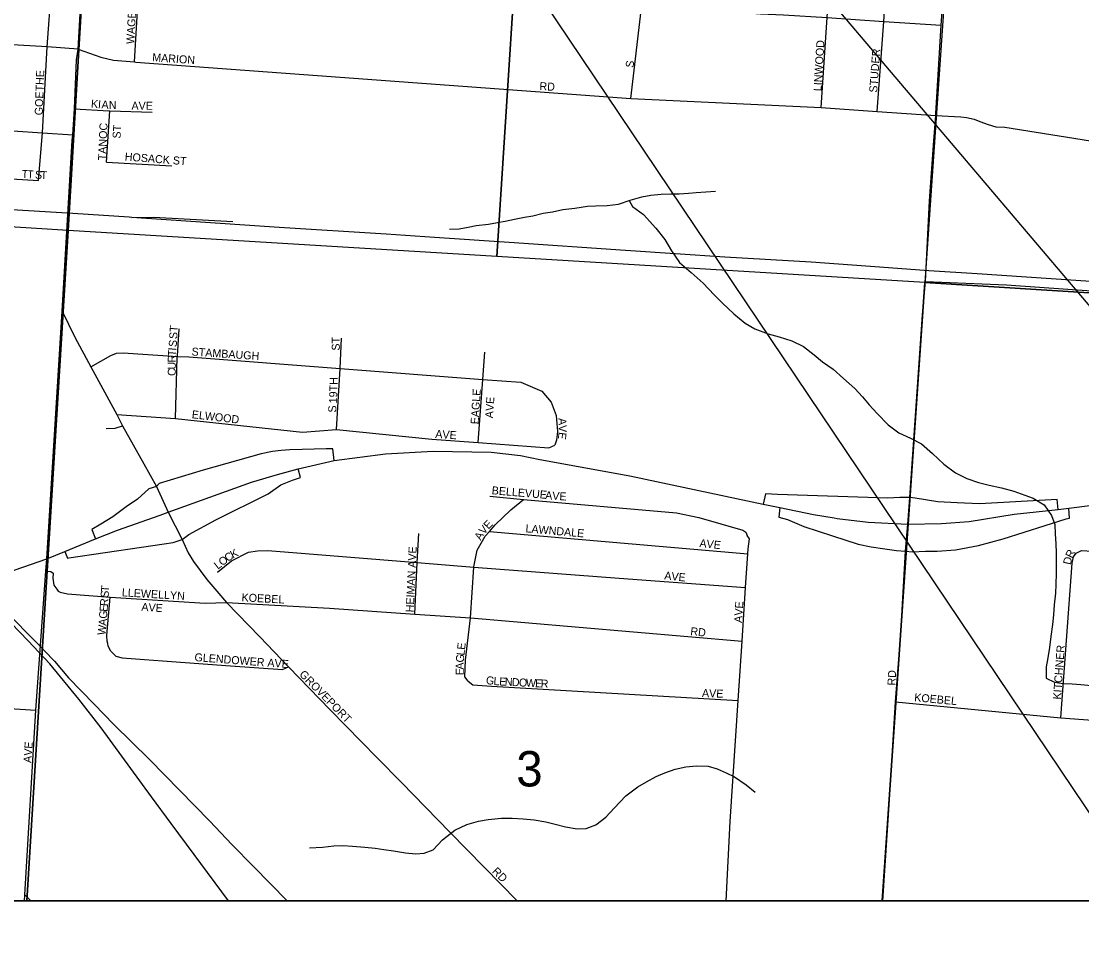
# Model space of a CAD drawing. Extents: x 0 to 34, y -6.2 to 22.
# Drawn here: x 7.442 to 8.697, y 14.325 to 15.431 of the extents above; entities that cross this region are included whole.
import ezdxf

# ---------------------------------------------------------------- set-up
doc = ezdxf.new("R2010")
doc.units = 0
for name, color, linetype in [('GM_X_City_Street', 7, 'Continuous'), ('GM_X_City_Street_Text', 7, 'Continuous'), ('GM_X_Corporation', 7, 'Continuous'), ('GM_X_Interchange_Ramps', 7, 'Continuous'), ('GM_X_Minor_River', 7, 'Continuous'), ('GM_X_Rail_Line', 7, 'Continuous'), ('GM_X_Section', 7, 'Continuous'), ('GM_X_Section_Text', 7, 'Continuous'), ('GM_X_State_Route', 7, 'Continuous'), ('SH_Data', 7, 'Continuous')]:
    doc.layers.add(name, color=color, linetype=linetype)

msp = doc.modelspace()

# ---------------------------------------------------------------- linework, layer by layer
at = {"layer": 'GM_X_City_Street'}
for points in [[(8.163, 15.3396), (8.176, 15.4504), (8.1782, 15.5559), (8.1782, 15.557), (8.1854, 15.613), (8.1897, 15.6855), (8.2011, 15.8649), (8.2084, 15.987), (8.2188, 16.1604)], [(8.524, 15.3221), (8.5303, 15.4266), (8.5334, 15.4708), (8.5376, 15.5324), (8.5419, 15.5889), (8.5466, 15.6592), (8.5554, 15.7853), (8.5577, 15.8394), (8.5686, 15.9805), (8.5712, 16.0212), (8.5785, 16.1374)], [(8.3883, 15.329), (8.3954, 15.4354), (8.4024, 15.5434)], [(8.4546, 15.3243), (8.4624, 15.4307), (8.4695, 15.5383)], [(7.5755, 15.383), (7.5841, 15.524)], [(7.4622, 15.2425), (7.4669, 15.299), (7.4724, 15.4007), (7.4775, 15.4705), (7.4788, 15.4923)], [(7.4902, 15.0879), (7.5019, 15.29), (7.5026, 15.2966), (7.5045, 15.3274), (7.5072, 15.3854), (7.5089, 15.3982), (7.5131, 15.4682)], [(8.1514, 15.4504), (8.176, 15.4504), (8.2417, 15.4455), (8.3166, 15.4399), (8.3436, 15.4388), (8.3954, 15.4354), (8.4624, 15.4307), (8.5303, 15.4266)], [(7.5089, 15.3982), (7.4724, 15.4007), (7.4381, 15.4029), (7.4099, 15.4045), (7.3643, 15.4074), (7.3253, 15.41), (7.3031, 15.4113), (7.2316, 15.4159), (7.1738, 15.4196), (7.1238, 15.4229), (7.0334, 15.4291), (6.9246, 15.436)], [(7.5089, 15.3982), (7.5358, 15.3885), (7.551, 15.3852), (7.5755, 15.383), (7.5774, 15.3828)], [(7.5774, 15.3828), (8.163, 15.3396), (8.3883, 15.329), (8.4546, 15.3243), (8.5238, 15.3195)], [(6.9278, 15.3347), (6.9941, 15.3301), (7.0268, 15.3278), (7.0575, 15.326), (7.088, 15.324), (7.1174, 15.3219), (7.1555, 15.3196), (7.1669, 15.3189), (7.2254, 15.3148), (7.2752, 15.3117), (7.3191, 15.3089), (7.358, 15.3062), (7.4217, 15.3018), (7.4319, 15.3013), (7.4669, 15.299), (7.5026, 15.2966)], [(7.5045, 15.3274), (7.5454, 15.3251)], [(7.5425, 15.2645), (7.5466, 15.3251)], [(7.5454, 15.3251), (7.5466, 15.3251), (7.5966, 15.3237)], [(8.5118, 15.1232), (8.5166, 15.2187), (8.5215, 15.2895), (8.5238, 15.3195), (8.524, 15.3221)], [(8.5238, 15.3195), (8.5536, 15.318), (8.5604, 15.3173), (8.5692, 15.3152), (8.5761, 15.3123), (8.586, 15.3089), (8.5948, 15.3063), (8.6058, 15.3058), (8.707, 15.2895), (8.7685, 15.2877), (8.792, 15.2886), (8.8262, 15.3), (8.8384, 15.3033), (8.8573, 15.3032), (8.8971, 15.3013), (9.0311, 15.3002)], [(7.5425, 15.2645), (7.6197, 15.2599)], [(7.4034, 15.2468), (7.4174, 15.2454), (7.4622, 15.2425)], [(8.4932, 14.8674), (8.5082, 15.0838), (8.5118, 15.1232)], [(8.5118, 15.1232), (8.6075, 15.1193), (9.0153, 15.0903), (9.0755, 15.0865)], [(7.4461, 14.3971), (7.459, 14.6158), (7.4708, 14.7803), (7.4718, 14.795), (7.4902, 15.0879)], [(7.4902, 15.0879), (7.5052, 15.0572), (7.5239, 15.0222), (7.5548, 14.9656), (7.5615, 14.9525), (7.5869, 14.9072)], [(7.6265, 15.0352), (7.6286, 15.067)], [(7.8148, 14.9479), (7.8191, 15.0202), (7.8205, 15.0561)], [(7.5239, 15.0222), (7.5477, 15.0354), (7.5544, 15.0382), (7.5622, 15.0388), (7.6264, 15.0343), (7.6401, 15.034), (7.8191, 15.0202), (7.988, 15.0072), (8.033, 15.0038), (8.0577, 14.9932), (8.0687, 14.9803), (8.0745, 14.9644), (8.0761, 14.9454), (8.075, 14.9352), (8.0731, 14.9295)], [(7.9873, 14.9965), (7.9873, 14.9966), (7.988, 15.0072), (7.9904, 15.0393)], [(7.6243, 14.9611), (7.6263, 15.0334), (7.6264, 15.0343), (7.6265, 15.0352)], [(7.9825, 14.9325), (7.9873, 14.9965)], [(7.5548, 14.9656), (7.6243, 14.9611), (7.7746, 14.9448), (7.8148, 14.9479), (7.9275, 14.9366), (7.9825, 14.9325), (8.0659, 14.9264), (8.0731, 14.9295)], [(7.5421, 14.949), (7.5527, 14.9497), (7.5615, 14.9525)], [(7.5869, 14.9072), (7.6019, 14.8804), (7.6155, 14.8501), (7.6322, 14.8177), (7.6393, 14.8019), (7.6456, 14.7917), (7.6613, 14.7706), (7.6731, 14.7568), (7.6847, 14.7433)], [(7.9706, 14.6501), (7.9664, 14.6554), (7.9674, 14.6748), (7.9733, 14.7249), (7.9773, 14.7852), (7.9773, 14.7853), (7.981, 14.805), (7.9908, 14.8218), (7.9956, 14.8272), (8.0025, 14.8351), (8.021, 14.853), (8.0361, 14.8653)], [(7.996, 14.8689), (8.0361, 14.8653), (8.2171, 14.8495), (8.2436, 14.8439), (8.2956, 14.8288), (8.2991, 14.8266), (8.3006, 14.8224)], [(8.4882, 14.8038), (8.4909, 14.8358), (8.4932, 14.8674)], [(7.9074, 14.7296), (7.9102, 14.7905), (7.9122, 14.8249)], [(7.9956, 14.8272), (8.3014, 14.801)], [(8.2758, 14.3902), (8.2805, 14.4841), (8.29, 14.6272), (8.2946, 14.6974), (8.2988, 14.7608), (8.3014, 14.801), (8.3018, 14.8068), (8.3033, 14.8186), (8.3006, 14.8224)], [(7.6738, 14.779), (7.6906, 14.7924), (7.7106, 14.8027), (7.7214, 14.8044), (7.7334, 14.8049), (7.9102, 14.7905), (7.9773, 14.7852), (8.1491, 14.7722), (8.2988, 14.7608)], [(8.4613, 14.3902), (8.4692, 14.5096), (8.4764, 14.6258), (8.4824, 14.7064), (8.4882, 14.8038)], [(8.672, 14.6067), (8.6853, 14.7899), (8.6869, 14.7971), (8.69, 14.8016)], [(8.69, 14.8016), (8.6965, 14.8046), (8.7405, 14.8019), (8.8201, 14.7971), (8.8276, 14.7928)], [(7.4708, 14.7803), (7.4767, 14.78), (7.4793, 14.7778), (7.4791, 14.7722), (7.4802, 14.7637), (7.4836, 14.759), (7.4852, 14.7568), (7.4878, 14.7555), (7.4963, 14.7534), (7.5469, 14.7497), (7.6592, 14.7423), (7.6847, 14.7433)], [(7.5477, 14.6855), (7.5447, 14.6917), (7.544, 14.6947), (7.5433, 14.6976), (7.5429, 14.7038), (7.5435, 14.7088), (7.5469, 14.7497)], [(7.6847, 14.7433), (7.8064, 14.7367), (7.9074, 14.7296), (7.9733, 14.7249), (8.2946, 14.6974)], [(7.6847, 14.7433), (7.724, 14.7026), (7.7581, 14.6671)], [(7.5477, 14.6855), (7.5534, 14.6798), (7.5612, 14.6777), (7.5876, 14.6758), (7.6089, 14.6743), (7.6894, 14.6684), (7.7508, 14.6641), (7.7581, 14.6671)], [(7.7581, 14.6671), (7.8072, 14.6161), (7.8628, 14.5594), (7.8916, 14.5301), (7.949, 14.4715), (7.9896, 14.43), (8.0286, 14.3902)], [(6.9277, 14.6512), (7.0759, 14.6409), (7.1676, 14.6348), (7.226, 14.6309), (7.2857, 14.6268), (7.459, 14.6158)], [(7.9706, 14.6501), (7.9759, 14.6459), (7.9983, 14.6441), (8.29, 14.6272)], [(8.4764, 14.6258), (8.672, 14.6067), (8.8111, 14.5964), (8.8376, 14.5944), (8.9733, 14.5845), (8.9736, 14.5844), (9.0374, 14.5797), (9.0755, 14.5768)], [(7.4455, 14.3902), (7.4461, 14.3971)], [(7.4529, 14.3902), (7.4461, 14.3971)]]:
    msp.add_lwpolyline(points, dxfattribs=at)
at = {"layer": 'GM_X_Corporation'}
msp.add_lwpolyline([(5.4833, 14.3902), (9.0755, 14.3902), (9.0755, 21.1902), (4.181, 21.1902)], dxfattribs=at)
at = {"layer": 'GM_X_Interchange_Ramps'}
for points in [[(7.8119, 14.9114), (7.8104, 14.9249), (7.8025, 14.9249), (7.7741, 14.9244), (7.7595, 14.9239), (7.7494, 14.9233), (7.739, 14.9219), (7.7255, 14.9191), (7.6568, 14.8999), (7.6048, 14.884), (7.6019, 14.8804)], [(7.6322, 14.8177), (7.6398, 14.8238), (7.672, 14.841), (7.7338, 14.872), (7.7489, 14.8824), (7.7625, 14.888), (7.7721, 14.8913), (7.7695, 14.9015)], [(7.6019, 14.8804), (7.5926, 14.8776), (7.5791, 14.8656), (7.566, 14.8563), (7.5499, 14.8448), (7.5357, 14.8359), (7.525, 14.8298), (7.5295, 14.8185)], [(8.4932, 14.8674), (8.4812, 14.8676), (8.467, 14.8668), (8.3367, 14.871), (8.3224, 14.872), (8.3224, 14.872), (8.3198, 14.8595)], [(8.6688, 14.8534), (8.6676, 14.8651), (8.5756, 14.8601), (8.5492, 14.8611), (8.5264, 14.8624), (8.4995, 14.8668), (8.4932, 14.8674)], [(8.3395, 14.8558), (8.338, 14.8443), (8.3485, 14.8413), (8.3677, 14.833), (8.4017, 14.822), (8.4319, 14.8121), (8.4473, 14.8091), (8.4635, 14.8069), (8.4775, 14.8049), (8.4882, 14.8038)], [(8.4882, 14.8038), (8.4963, 14.8032), (8.5119, 14.8038), (8.5257, 14.8038), (8.5474, 14.8056), (8.5746, 14.8106), (8.6037, 14.8185), (8.6782, 14.8424), (8.6822, 14.8432), (8.6813, 14.8549)], [(7.4933, 14.8037), (7.4965, 14.7957), (7.4979, 14.796), (7.584, 14.8086), (7.6109, 14.8126), (7.6213, 14.8141), (7.6322, 14.8177)]]:
    msp.add_lwpolyline(points, dxfattribs=at)
at = {"layer": 'GM_X_Minor_River'}
for points in [[(7.9486, 15.185), (7.9599, 15.1853), (7.9706, 15.1874), (7.98, 15.1893), (7.9948, 15.191), (8.0051, 15.1929), (8.0145, 15.1947), (8.0255, 15.1969), (8.0373, 15.1991), (8.0472, 15.2009), (8.0593, 15.2038), (8.0703, 15.2056), (8.0825, 15.2082), (8.0969, 15.21), (8.1116, 15.2121), (8.1211, 15.2128), (8.1351, 15.2131), (8.1484, 15.2145), (8.1621, 15.2193), (8.1761, 15.2234), (8.1867, 15.2252), (8.1989, 15.2266), (8.2102, 15.2269), (8.2201, 15.2268), (8.2311, 15.2278), (8.2405, 15.2285), (8.2633, 15.2299)], [(8.161, 15.2189), (8.165, 15.2117), (8.1782, 15.2025), (8.1928, 15.1864), (8.2033, 15.1727), (8.2111, 15.1593), (8.2208, 15.1456), (8.2343, 15.1337), (8.2486, 15.1211), (8.2617, 15.1073), (8.2711, 15.0977), (8.285, 15.0847), (8.2985, 15.074), (8.3098, 15.0671), (8.3256, 15.0612), (8.3385, 15.0577), (8.3536, 15.053), (8.3675, 15.0461), (8.3799, 15.0365), (8.3897, 15.0281), (8.4025, 15.0192), (8.4149, 15.0085), (8.428, 14.9963), (8.437, 14.9867), (8.4449, 14.9772), (8.4546, 14.9668), (8.4674, 14.9534), (8.4801, 14.9439), (8.4941, 14.9377), (8.5069, 14.9311), (8.5201, 14.9196), (8.5336, 14.907), (8.5471, 14.8966), (8.5607, 14.8901), (8.5743, 14.8854), (8.5871, 14.8819), (8.6018, 14.8791), (8.6162, 14.8748), (8.6294, 14.8702), (8.6392, 14.8667), (8.652, 14.859), (8.661, 14.846), (8.6647, 14.8357), (8.6653, 14.8243), (8.6659, 14.8126), (8.6662, 14.8019), (8.6665, 14.7887), (8.6664, 14.778), (8.6659, 14.7647), (8.6654, 14.7541), (8.6641, 14.7405), (8.6633, 14.7287), (8.662, 14.717), (8.66, 14.7029), (8.6583, 14.6901), (8.6567, 14.6779), (8.6547, 14.6669), (8.6546, 14.6537), (8.6644, 14.649), (8.6746, 14.6474), (8.6852, 14.647), (8.6954, 14.6461), (8.7083, 14.6449)], [(7.7826, 14.4528), (7.7981, 14.4538), (7.8117, 14.4552), (7.8223, 14.4555), (7.8337, 14.455), (7.8481, 14.4538), (7.8606, 14.4525), (7.8708, 14.4509), (7.8821, 14.4493), (7.8965, 14.4469), (7.9086, 14.4457), (7.9184, 14.4464), (7.9291, 14.4505), (7.9402, 14.4625), (7.9547, 14.4738), (7.9691, 14.4805), (7.9828, 14.4846), (7.9942, 14.4864), (8.0101, 14.4881), (8.0226, 14.488), (8.0358, 14.4872), (8.0487, 14.4859), (8.0623, 14.4835), (8.0736, 14.4808), (8.0857, 14.4776), (8.0997, 14.4753), (8.1103, 14.4756), (8.1217, 14.48), (8.1335, 14.489), (8.1435, 14.4999), (8.1572, 14.5143), (8.1713, 14.5251), (8.1816, 14.5311), (8.193, 14.5371), (8.2033, 14.5416), (8.2155, 14.546), (8.228, 14.5486), (8.2409, 14.55), (8.2545, 14.5495), (8.2651, 14.5464), (8.276, 14.5418), (8.2858, 14.5367), (8.2994, 14.5275), (8.3102, 14.5187)]]:
    msp.add_lwpolyline(points, dxfattribs=at)
at = {"layer": 'GM_X_Rail_Line'}
for points in [[(7.5026, 15.2037), (7.4307, 15.2081), (7.3437, 15.2139), (7.2824, 15.2183), (7.2084, 15.2228), (7.144, 15.2272), (7.069, 15.2322), (7.0427, 15.2341), (7.0233, 15.2363), (7.006, 15.2393), (6.9959, 15.2417), (6.9866, 15.2441), (6.9688, 15.2499), (6.9554, 15.2553), (6.9443, 15.2608), (6.9274, 15.2702)], [(7.6869, 14.3902), (7.6461, 14.4451), (7.6191, 14.4818), (7.5959, 14.5134), (7.5363, 14.5949), (7.5097, 14.6288), (7.4754, 14.6708), (7.45, 14.698), (7.3488, 14.8025), (7.2927, 14.8586), (7.1166, 15.0392), (7.0016, 15.1599), (6.9277, 15.2368)], [(6.9277, 15.2368), (7.064, 15.1049), (7.1411, 15.0259), (7.152, 15.014), (7.2103, 14.9543), (7.294, 14.8686), (7.3646, 14.797), (7.426, 14.7299), (7.4578, 14.698), (7.4811, 14.6739), (7.4975, 14.654), (7.5279, 14.6228), (7.5514, 14.5987), (7.5933, 14.5576), (7.6647, 14.4843), (7.6908, 14.457), (7.7165, 14.4308), (7.7565, 14.3902)], [(7.5724, 15.199), (7.5694, 15.1992), (7.5026, 15.2037)], [(7.5724, 15.199), (7.5987, 15.1992), (7.692, 15.1941)], [(9.0755, 15.0988), (9.0049, 15.103), (8.573, 15.1323), (8.5158, 15.1357), (8.4572, 15.1401), (8.3764, 15.146), (8.2742, 15.1521), (8.1569, 15.1599), (8.019, 15.1693), (7.9307, 15.1752), (7.8737, 15.179), (7.747, 15.1872), (7.5724, 15.199)]]:
    msp.add_lwpolyline(points, dxfattribs=at)
at = {"layer": 'GM_X_Section'}
for p, q in [((6.449, 14.3902), (7.4483, 14.3902)), ((7.4483, 14.3902), (8.4604, 14.3902))]:
    msp.add_line(p, q, dxfattribs=at)
for points in [[(7.5576, 16.2055), (7.497, 15.1834), (6.5086, 15.2458), (6.5658, 16.0353), (6.5704, 16.0443), (6.5735, 16.0466), (6.5731, 16.0496), (6.5693, 16.0527), (6.5637, 16.0565), (6.5603, 16.0599), (6.5603, 16.0637), (6.5622, 16.0671), (6.5676, 16.0735), (6.582, 16.0863), (6.5935, 16.0976), (6.6121, 16.1149), (6.632, 16.1352), (6.6415, 16.1465), (6.6507, 16.159), (6.658, 16.1722), (6.671, 16.2039), (6.6853, 16.2364), (6.6948, 16.25), (6.6949, 16.2608)], [(7.5576, 16.2055), (8.0698, 16.171), (8.0045, 15.1527), (7.497, 15.1834)], [(8.0698, 16.171), (8.5808, 16.1366), (8.5108, 15.1221), (8.0045, 15.1527)]]:
    msp.add_lwpolyline(points, close=True, dxfattribs=at)
for points in [[(9.0755, 16.1062), (8.5808, 16.1366), (8.5108, 15.1221), (9.0132, 15.0904), (9.0755, 15.9856)], [(7.4483, 14.3902), (7.497, 15.1834), (6.5086, 15.2458), (6.449, 14.3902)], [(8.4604, 14.3902), (8.5108, 15.1221), (8.0045, 15.1527), (7.497, 15.1834), (7.4483, 14.3902)], [(9.0755, 15.0865), (9.0132, 15.0904), (8.5108, 15.1221), (8.4604, 14.3902)], [(8.4604, 14.3902), (9.0755, 14.3902), (9.0755, 15.0865)]]:
    msp.add_lwpolyline(points, dxfattribs=at)
at = {"layer": 'GM_X_State_Route'}
for points in [[(7.6059, 14.8467), (7.6155, 14.8501), (7.7143, 14.8855), (7.7451, 14.8948), (7.7695, 14.9015), (7.8119, 14.9114), (7.8726, 14.9191), (7.9293, 14.9225), (7.9977, 14.9211), (8.0324, 14.9172), (8.0554, 14.9123), (8.162, 14.8932), (8.3198, 14.8595), (8.3395, 14.8558), (8.3793, 14.8475), (8.4038, 14.8434)], [(6.9294, 14.8673), (6.9842, 14.8611), (7.0094, 14.8593), (7.0291, 14.8563), (7.0489, 14.8511), (7.0841, 14.8378), (7.0937, 14.8337), (7.1333, 14.816), (7.1612, 14.805), (7.1885, 14.7926), (7.2087, 14.7837), (7.2361, 14.7743), (7.2834, 14.7621), (7.3121, 14.7585), (7.3733, 14.7628), (7.4146, 14.775), (7.4718, 14.795), (7.4933, 14.8037), (7.5295, 14.8185), (7.5554, 14.829), (7.6059, 14.8467)], [(8.4038, 14.8434), (8.4072, 14.8428), (8.444, 14.8384), (8.4909, 14.8358), (8.5308, 14.8367), (8.5634, 14.8389), (8.6165, 14.8479), (8.6688, 14.8534), (8.6813, 14.8549), (8.7093, 14.8583), (8.742, 14.8609), (8.7779, 14.8635), (8.8417, 14.8645), (8.9945, 14.8518), (9.0755, 14.8466)]]:
    msp.add_lwpolyline(points, dxfattribs=at)
at = {"layer": 'SH_Data'}
for points in [[(9.0755, 21.1902), (9.0755, 14.3902), (2.2755, 14.3902), (2.2755, 21.1902)], [(9.8345, 13.7654), (6.7618, 17.3841), (9.8345, 12.8156)]]:
    msp.add_lwpolyline(points, close=True, dxfattribs=at)

# ---------------------------------------------------------------- texts
at = {"layer": 'GM_X_City_Street_Text'}
for s, rotation, p in [('WAGER ST', 86.7772, (7.5753, 15.4039)), ('LINWOOD', 86.5305, (8.3886, 15.3481)), ('MARION', 355.9166, (7.5964, 15.3839)), ('STUDER', 85.766, (8.4545, 15.3464)), ('S', 82.8783, (8.1661, 15.3757)), ('GOETHE', 87.9557, (7.467, 15.3197)), ('RD', 356.989, (8.0547, 15.3497)), ('K', 355.7991, (7.5239, 15.3289)), ('I', 355.7991, (7.5322, 15.3283)), ('A', 356.1082, (7.5364, 15.328)), ('N', 358.9569, (7.5452, 15.3274)), ('AVE', 0, (7.5721, 15.3264)), ('TANOC', 87.6154, (7.542, 15.2664)), ('ST', 86.4254, (7.5591, 15.2921)), ('HOSACK ST', 355.5442, (7.5639, 15.2664)), ('T', 356.6095, (7.4419, 15.2458)), ('T', 356.6446, (7.4485, 15.2454)), ('S', 356.6111, (7.4577, 15.2449)), ('T', 356.6588, (7.4643, 15.2445)), ('ST', 86.1879, (7.6261, 15.0547)), ('S', 84.2812, (7.6254, 15.0452)), ('ST', 90, (7.8186, 15.0413)), ('T', 85.9533, (7.6246, 15.0344)), ('I', 84.5286, (7.625, 15.041)), ('STAMBAUGH', 356.0546, (7.643, 15.0356)), ('R', 89.32, (7.6245, 15.0271)), ('U', 89.9344, (7.6245, 15.0188)), ('C', 89.9514, (7.6245, 15.0113)), ('19TH', 88.2111, (7.8153, 14.9788)), ('EAGLE', 86.266, (7.9828, 14.9539)), ('AVE', 86.0494, (7.9999, 14.9611)), ('S', 90, (7.8145, 14.968)), ('ELWOOD', 353.3458, (7.6431, 14.9614)), ('A', 272.3177, (8.0772, 14.9614)), ('V', 271.3551, (8.0775, 14.9531)), ('AVE', 356.0569, (7.9314, 14.9381)), ('E', 262.6852, (8.0777, 14.9452)), ('BELLEVUE', 355.1691, (7.9981, 14.8714)), ('AVE', 356.0499, (8.0614, 14.8656)), ('V', 49.439, (7.9893, 14.823)), ('E', 46.9709, (7.9946, 14.8292)), ('LAWNDALE', 354.872, (8.0381, 14.8264)), ('A', 60.3744, (7.9854, 14.8161)), ('AVE', 354.0895, (8.2439, 14.8089)), ('O', 37.7461, (7.6796, 14.7859)), ('C', 33.7305, (7.686, 14.7909)), ('K', 28.6576, (7.6921, 14.795)), ('HEIMAN AVE', 87.3963, (7.9061, 14.7314)), ('R', 63.8694, (8.6852, 14.7949)), ('L', 37.7168, (7.6743, 14.7819)), ('D', 77.7343, (8.6836, 14.7873)), ('AVE', 354.0969, (8.2023, 14.7706)), ('T', 85.7878, (7.5454, 14.7553)), ('LLEWELLYN', 356.5928, (7.5605, 14.7506)), ('R', 85.795, (7.5441, 14.7386)), ('S', 85.809, (7.5449, 14.7486)), ('KOEBEL', 356.8756, (7.7022, 14.7447)), ('E', 85.7986, (7.5437, 14.732)), ('AVE', 356.0494, (7.5836, 14.7335)), ('AVE', 86.0569, (8.2945, 14.7189)), ('A', 85.6798, (7.5424, 14.7154)), ('G', 85.7815, (7.543, 14.7237)), ('W', 83.5465, (7.5412, 14.7042)), ('RD', 353.9946, (8.2331, 14.7047)), ('L', 83.2646, (7.966, 14.6801)), ('E', 83.1529, (7.9667, 14.6868)), ('KITCHNER', 85.9135, (8.672, 14.6281)), ('GLENDOWER AVE', 355.7113, (7.6464, 14.6739)), ('A', 89.7158, (7.9653, 14.6638)), ('G', 85.6901, (7.9653, 14.6719)), ('GROVEPORT', 314.5087, (7.77, 14.6575)), ('E', 89.8907, (7.9653, 14.6571)), ('RD', 86.9769, (8.4761, 14.6447)), ('G', 349.7831, (7.9909, 14.6472)), ('L', 356.3154, (8.0003, 14.6456)), ('E', 357.1649, (8.0071, 14.6451)), ('N', 357.1781, (8.0137, 14.6448)), ('D', 357.1791, (8.022, 14.6444)), ('O', 357.1572, (8.0304, 14.644)), ('W', 357.1707, (8.0387, 14.6436)), ('E', 357.1757, (8.0495, 14.643)), ('R', 357.157, (8.0562, 14.6427)), ('AVE', 358.0261, (8.2471, 14.6314)), ('KOEBEL', 354.7129, (8.4981, 14.6264)), ('AVE', 86.0569, (7.4536, 14.5531)), ('RD', 315.0084, (7.9983, 14.4242))]:
    msp.add_text(s, height=0.00947, rotation=rotation, dxfattribs=at).set_placement(p)
at = {"layer": 'GM_X_Section_Text'}
msp.add_text('3', height=0.0419, rotation=0, dxfattribs=at).set_placement((8.0275, 14.5255))

doc.saveas('drawing.dxf')
